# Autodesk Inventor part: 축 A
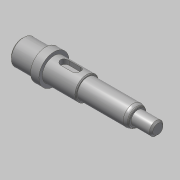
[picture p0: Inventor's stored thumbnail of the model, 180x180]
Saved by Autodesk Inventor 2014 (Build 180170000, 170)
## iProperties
Created: 2020-04
Part Number: 축 A
Material: 강철, 연강
Document SubType Name: Modeling
Designer: mduedu
Density: 1 g/cm^3
Appearance: 강철
Author: mduedu
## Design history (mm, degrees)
sketch "스케치1"
  geometry: L1 (0, 0)-(14, 0); L2 (14, 0)-(14, 7.5); L3 (14, 7.5)-(0, 7.5); L4 (0, 7.5)-(0, 0); L5 (14, 0)-(19, 0); L6 (19, 0)-(19, 9); L7 (19, 9)-(14, 9); L8 (14, 9)-(14, 0); L9 (19, 0)-(39, 0); L10 (39, 0)-(39, 7); L11 (39, 7)-(19, 7); L12 (19, 7)-(19, 0); L13 (39, 0)-(69, 0); L14 (69, 0)-(69, 6); L15 (69, 6)-(39, 6); L16 (39, 6)-(39, 0); L17 (69, 0)-(81, 0); L18 (81, 0)-(81, 4); L19 (81, 4)-(69, 4); L20 (69, 4)-(69, 0)
  constraints: 40 end point, 10 parallel, 5 horizontal, 5 perpendicular
  dimensions: "d0" = 81 distance between parallel lines of L18 L4; "d2" = 14 distance of L2.end L3.end; "d3" = 5 distance of L6.end L7.end; "d4" = 12 distance of L18.end L19.end; "d5" = 8 diameter of L19 L17; "d6" = 12 diameter of L15 L13; "d7" = 14 diameter of L11 L9; "d8" = 15 diameter of L3 L1; "d9" = 18 diameter of L7 L5; "d10" = 42 distance between parallel lines of L10 L18
revolve "회전1" sketch "스케치1" stored, may be unused: angle "d11" = 90 deg
sketch "스케치2"
  geometry: L1 (0, -7.5)-(0, 7.5) reference; L2 (0, 7.5)-(14, 7.5) reference; L3 (14, 7.5)-(14, 9) reference; L4 (14, 9)-(19, 9) reference; L5 (19, 9)-(19, 7) reference; L6 (19, 7)-(39, 7) reference; L7 (39, 7)-(39, 6) reference; L8 (39, 6)-(69, 6) reference; L9 (69, 6)-(69, 4) reference; L10 (69, 4)-(81, 4) reference; L11 (81, 4)-(81, -4) reference; L12 (81, -4)-(69, -4) reference; L13 (69, -4)-(69, -6) reference; L14 (69, -6)-(39, -6) reference; L15 (39, -6)-(39, -7) reference; L16 (39, -7)-(19, -7) reference; L17 (19, -7)-(19, -9) reference; L18 (19, -9)-(14, -9) reference; L19 (14, -9)-(14, -7.5) reference; L20 (14, -7.5)-(0, -7.5) reference; L21 (81, -4)-(73, -4); L22 (73, -4)-(73, -2.8); L23 (73, -2.8)-(81, -2.8); L24 (81, -2.8)-(81, -4); 1 further point
  constraints: 8 end point, 2 parallel, 1 horizontal, 1 perpendicular
  dimensions: "d12" = 8 distance of L22.end L23.end; "d13" = 1.2 distance of L21.end L22.end
extrude "돌출1" cut sketch "스케치2" stored distance "d14" = 2; taper "d15" = 0 deg
fillet "모깎기1" dims "d16" = 1
sketch "스케치3"
  geometry: L1 (0, -7.5)-(0, 7.5) reference; L2 (0, 7.5)-(14, 7.5) reference; L3 (14, 7.5)-(14, 9) reference; L4 (14, 9)-(19, 9) reference; L5 (19, 9)-(19, 7) reference; L6 (19, 7)-(39, 7) reference; L7 (39, 7)-(39, 6) reference; L8 (39, 6)-(69, 6) reference; L9 (69, 6)-(69, 4) reference; L10 (69, 4)-(81, 4) reference; L11 (81, 4)-(81, -2.8) reference; L12 (81, -2.8)-(73, -2.8) reference; L13 (73, -2.8)-(73, -4) reference; L14 (73, -4)-(69, -4) reference; L15 (69, -4)-(69, -6) reference; L16 (69, -6)-(39, -6) reference; L17 (39, -6)-(39, -7) reference; L18 (39, -7)-(19, -7) reference; L19 (19, -7)-(19, -9) reference; L20 (19, -9)-(14, -9) reference; L21 (14, -9)-(14, -7.5) reference; L22 (14, -7.5)-(0, -7.5) reference; L23 (23, 7)-(35, 7); L24 (35, 7)-(35, 4); L25 (35, 4)-(23, 4); L26 (23, 4)-(23, 7); 1 further point
  constraints: 8 end point, 2 parallel, 1 horizontal, 1 perpendicular, 1 point on line
  dimensions: "d17" = 12 distance of L24.end L25.end; "d18" = 3 distance of L23.end L24.end; "d19" = 4 distance from line of L26 L4.end
extrude "돌출2" cut sketch "스케치3" stored distance "d20" = 5; taper "d21" = 0 deg
fillet "모깎기2" dims "d22" = 2.5
chamfer "모따기1" distance "d23" = 1; stored, may be unused: second distance "d24" = 2, angle "d25" = 45 deg
chamfer "모따기2" distance "d26" = 0.5; stored, may be unused: second distance "d27" = 2, angle "d28" = 45 deg
fillet "모깎기3" dims "d29" = 0.3
chamfer "모따기3" distance "d30" = 1.56; stored, may be unused: second distance "d31" = 2, angle "d32" = 30 deg
fillet "모깎기4" dims "d33" = 4, "d34" = 0.5
node "솔리드1"
node "절단 모서리 투영1"
node "절단 모서리 투영2"
